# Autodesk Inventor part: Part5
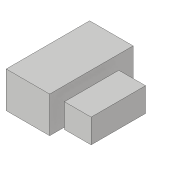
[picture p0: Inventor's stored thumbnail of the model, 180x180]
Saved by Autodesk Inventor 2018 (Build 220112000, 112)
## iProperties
Created: 2015-07
Part Number: Part5
Material: Generic
Document SubType Name: Modeling
Designer: Sandeep
Density: 1 g/cm^3
Appearance: Default
Author: Sandeep
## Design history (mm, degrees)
sketch "Sketch1"
  geometry: L1 (-7.411, 3.941)-(-1.385, 3.941); L2 (-1.385, 3.941)-(-1.385, -7.628); L3 (-1.385, -7.628)-(-7.411, -7.628); L4 (-7.411, -7.628)-(-7.411, 3.941); 1 further point
  constraints: 8 end point, 2 parallel, 1 horizontal, 1 perpendicular
extrude "Extrusion1" new body sketch "Sketch1" distance "d0" = 5; taper "d1" = 0 deg
sketch "Sketch2"
  geometry: L1 (1.52, -7.467)-(7.078, -7.467); L2 (7.078, -7.467)-(7.078, 3.854); L3 (7.078, 3.854)-(1.52, 3.854); L4 (1.52, 3.854)-(1.52, -7.467); 1 further point
  constraints: 8 end point, 2 parallel, 1 horizontal, 1 perpendicular
extrude "Extrusion2" new body sketch "Sketch2" distance "d2" = 5; taper "d3" = 0 deg
node "Direct Edit1"
body "Solid1"
body "Solid2"
feature "Scale1"
other parameters: "d4" = 15
